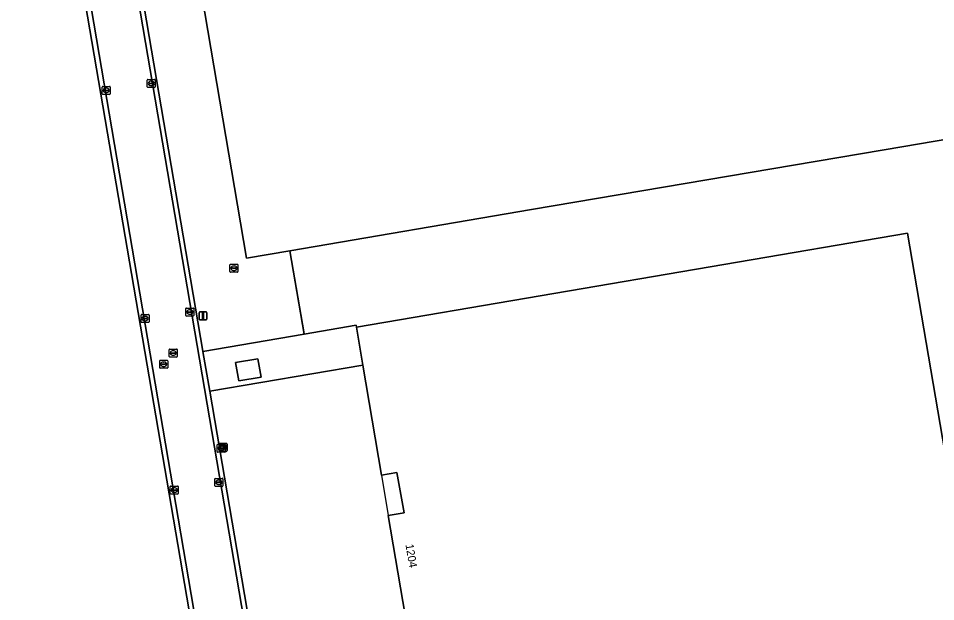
# Model space of a CAD drawing. Extents: x 154324 to 155744, y 382937 to 384188.
# Drawn here: x 154705 to 154819.6, y 383454.6 to 383527.5 of the extents above; entities that cross this region are included whole.
import ezdxf

# ---------------------------------------------------------------- set-up
doc = ezdxf.new("R2010")
doc.units = 0
for name, color, linetype in [('IMGEO_Brandkraan', 7, 'Continuous'), ('IMGEO_Erf', 7, 'Continuous'), ('IMGEO_Groenvoorziening', 7, 'Continuous'), ('IMGEO_Hek', 7, 'Continuous'), ('IMGEO_Kolk', 7, 'Continuous'), ('IMGEO_Lage_trafo', 7, 'Continuous'), ('IMGEO_Lichtmast', 7, 'Continuous'), ('IMGEO_Pand', 7, 'Continuous'), ('IMGEO_Pand_nummerreeks', 7, 'Continuous'), ('IMGEO_Pand_overbouw', 7, 'Continuous'), ('IMGEO_Parkeervlak_open', 7, 'Continuous'), ('IMGEO_Rijbaan_lokaal_gesloten', 7, 'Continuous'), ('IMGEO_Rijbaan_lokaal_open', 7, 'Continuous'), ('IMGEO_Rioolput', 7, 'Continuous'), ('IMGEO_Terreindeel_open', 7, 'Continuous'), ('IMGEO_Verklikker', 7, 'Continuous'), ('IMGEO_Voetpad_open', 7, 'Continuous')]:
    doc.layers.add(name, color=color, linetype=linetype)

msp = doc.modelspace()

# ---------------------------------------------------------------- linework, layer by layer
at = {"layer": 'IMGEO_Brandkraan'}
for p, q in [((154729.88, 383473.37), (154729.88, 383474.22)), ((154729.95, 383474.29), (154730.8, 383474.29)), ((154730.8, 383473.29), (154729.95, 383473.29)), ((154730.13, 383473.79), (154730.13, 383473.8)), ((154730.57, 383473.75), (154730.17, 383473.75)), ((154730.18, 383473.84), (154730.58, 383473.84)), ((154730.36, 383474.07), (154730.39, 383474.07)), ((154730.39, 383473.51), (154730.36, 383473.51)), ((154730.62, 383473.8), (154730.62, 383473.79)), ((154730.88, 383474.22), (154730.88, 383473.37))]:
    msp.add_line(p, q, dxfattribs=at)
for points in [[(154729.88, 383473.37), (154729.88, 383474.22)], [(154729.95, 383474.29), (154730.8, 383474.29)], [(154730.8, 383473.29), (154729.95, 383473.29)], [(154730.88, 383474.22), (154730.88, 383473.37)]]:
    msp.add_lwpolyline(points, dxfattribs=at)
for centre, radius, start, end in [((154729.95, 383474.22), 0.0765, 91.552, 178.448), ((154729.95, 383474.22), 0.0765, 91.552, 178.448), ((154729.95, 383473.37), 0.0765, 181.552, 268.448), ((154729.95, 383473.37), 0.0765, 181.552, 268.448), ((154730.18, 383473.8), 0.0403, 85.8775, 175.7526), ((154730.17, 383473.79), 0.0366, 178.938, 274.7102), ((154730.58, 383473.79), 0.043, 264.8664, 352.4533), ((154730.58, 383473.8), 0.0386, 1.7309, 96.639), ((154730.8, 383474.22), 0.0765, 1.552, 88.448), ((154730.8, 383474.22), 0.0765, 1.552, 88.448), ((154730.8, 383473.37), 0.0765, 271.552, 358.448), ((154730.8, 383473.37), 0.0765, 271.552, 358.448)]:
    msp.add_arc(centre, radius, start, end, dxfattribs=at)
for centre, major_axis, ratio, start_param, end_param in [((154730.36, 383473.79), (-0.387, 0.002), 0.722429, 4.712389, 7.853982), ((154730.39, 383473.79), (-0.39, 0.002), 0.717154, 1.570796, 4.712389)]:
    msp.add_ellipse(centre, major_axis=major_axis, ratio=ratio, start_param=start_param, end_param=end_param, dxfattribs=at)
at = {"layer": 'IMGEO_Erf'}
msp.add_lwpolyline([(154895.55, 383525.1), (154815.63, 383511.49), (154769.14, 383503.59), (154738.94, 383498.45), (154740.73, 383488.05), (154747.21, 383489.16), (154747.25, 383488.9), (154816.1, 383500.63), (154832.97, 383401.91), (154774.29, 383391.51), (154774.27, 383391.62), (154764.11, 383389.85), (154762.79, 383389.63), (154771.19, 383339.88), (154753.52, 383336.76), (154753.64, 383336.06), (154760.59, 383295.34), (154764.66, 383271.37), (154789.97, 383122.38), (154790.21, 383121.25)], dxfattribs=at)
at = {"layer": 'IMGEO_Groenvoorziening'}
msp.add_lwpolyline([(154736.07, 383396.59), (154735.43, 383400.34), (154733.72, 383410.4), (154733.05, 383414.37), (154731.57, 383423.07), (154705.98, 383572.84)], dxfattribs=at)
at = {"layer": 'IMGEO_Hek'}
msp.add_lwpolyline([(154738.94, 383498.45), (154740.73, 383488.07)], dxfattribs=at)
at = {"layer": 'IMGEO_Kolk'}
for p, q in [((154721.13, 383518.92), (154721.13, 383519.77)), ((154721.2, 383519.84), (154722.06, 383519.84)), ((154721.39, 383519.34), (154721.39, 383519.35)), ((154721.43, 383519.39), (154721.83, 383519.39)), ((154721.83, 383519.3), (154721.43, 383519.3)), ((154721.62, 383519.62), (154721.64, 383519.62)), ((154721.64, 383519.06), (154721.62, 383519.06)), ((154721.87, 383519.35), (154721.87, 383519.34)), ((154722.13, 383519.77), (154722.13, 383518.92)), ((154715.5, 383518.05), (154715.5, 383518.9)), ((154715.57, 383518.98), (154716.43, 383518.98)), ((154716.43, 383517.98), (154715.57, 383517.98)), ((154715.76, 383518.47), (154715.76, 383518.48)), ((154715.8, 383518.52), (154716.2, 383518.52)), ((154716.2, 383518.43), (154715.8, 383518.43)), ((154715.99, 383518.76), (154716.01, 383518.76)), ((154716.01, 383518.2), (154715.99, 383518.2)), ((154716.24, 383518.48), (154716.24, 383518.47)), ((154716.5, 383518.9), (154716.5, 383518.05)), ((154722.06, 383518.84), (154721.2, 383518.84)), ((154720.35, 383489.57), (154720.35, 383490.42)), ((154720.42, 383490.49), (154721.28, 383490.49)), ((154721.35, 383490.42), (154721.35, 383489.57)), ((154725.95, 383490.37), (154725.95, 383491.23)), ((154726.02, 383491.3), (154726.87, 383491.3)), ((154726.2, 383490.79), (154726.2, 383490.81)), ((154726.64, 383490.76), (154726.24, 383490.76)), ((154726.25, 383490.84), (154726.64, 383490.84)), ((154726.43, 383491.08), (154726.46, 383491.08)), ((154726.46, 383490.52), (154726.43, 383490.52)), ((154726.69, 383490.81), (154726.69, 383490.79)), ((154726.95, 383491.23), (154726.95, 383490.37)), ((154721.28, 383489.49), (154720.42, 383489.49)), ((154720.61, 383489.99), (154720.61, 383490)), ((154720.65, 383490.04), (154721.05, 383490.04)), ((154721.05, 383489.95), (154720.65, 383489.95)), ((154720.86, 383489.71), (154720.83, 383489.71)), ((154720.84, 383490.27), (154720.86, 383490.27)), ((154721.09, 383490), (154721.09, 383489.99)), ((154726.87, 383490.3), (154726.02, 383490.3)), ((154729.57, 383469.11), (154729.57, 383469.96)), ((154729.65, 383470.03), (154730.5, 383470.03)), ((154730.06, 383469.81), (154730.09, 383469.81)), ((154730.57, 383469.96), (154730.57, 383469.11)), ((154724, 383468.14), (154724, 383469)), ((154724.07, 383469.07), (154724.93, 383469.07)), ((154724.26, 383468.56), (154724.26, 383468.58)), ((154724.3, 383468.61), (154724.7, 383468.61)), ((154724.49, 383468.85), (154724.51, 383468.85)), ((154724.74, 383468.58), (154724.74, 383468.56)), ((154725, 383469), (154725, 383468.14)), ((154730.5, 383469.03), (154729.65, 383469.03)), ((154729.83, 383469.53), (154729.83, 383469.54)), ((154729.87, 383469.58), (154730.27, 383469.58)), ((154730.27, 383469.49), (154729.87, 383469.49)), ((154730.08, 383469.25), (154730.06, 383469.25)), ((154730.32, 383469.54), (154730.32, 383469.53)), ((154724.93, 383468.07), (154724.07, 383468.07)), ((154724.69, 383468.53), (154724.3, 383468.53)), ((154724.51, 383468.29), (154724.48, 383468.29))]:
    msp.add_line(p, q, dxfattribs=at)
for points in [[(154721.13, 383518.92), (154721.13, 383519.77)], [(154721.2, 383519.84), (154722.06, 383519.84)], [(154722.13, 383519.77), (154722.13, 383518.92)], [(154715.5, 383518.05), (154715.5, 383518.9)], [(154715.57, 383518.98), (154716.43, 383518.98)], [(154716.43, 383517.98), (154715.57, 383517.98)], [(154716.5, 383518.9), (154716.5, 383518.05)], [(154722.06, 383518.84), (154721.2, 383518.84)], [(154720.35, 383489.57), (154720.35, 383490.42)], [(154720.42, 383490.49), (154721.28, 383490.49)], [(154721.35, 383490.42), (154721.35, 383489.57)], [(154725.95, 383490.37), (154725.95, 383491.23)], [(154726.02, 383491.3), (154726.87, 383491.3)], [(154726.95, 383491.23), (154726.95, 383490.37)], [(154721.28, 383489.49), (154720.42, 383489.49)], [(154726.87, 383490.3), (154726.02, 383490.3)], [(154729.57, 383469.11), (154729.57, 383469.96)], [(154729.65, 383470.03), (154730.5, 383470.03)], [(154730.57, 383469.96), (154730.57, 383469.11)], [(154724, 383468.14), (154724, 383469)], [(154724.07, 383469.07), (154724.93, 383469.07)], [(154725, 383469), (154725, 383468.14)], [(154730.5, 383469.03), (154729.65, 383469.03)], [(154724.93, 383468.07), (154724.07, 383468.07)]]:
    msp.add_lwpolyline(points, dxfattribs=at)
for centre, radius, start, end in [((154721.21, 383519.77), 0.0765, 91.552, 178.448), ((154721.21, 383519.77), 0.0765, 91.552, 178.448), ((154721.43, 383519.35), 0.0403, 85.8775, 175.7526), ((154721.43, 383519.34), 0.0366, 178.938, 274.7102), ((154721.83, 383519.35), 0.0386, 1.7309, 96.639), ((154721.83, 383519.34), 0.043, 264.8664, 352.4533), ((154722.05, 383519.77), 0.0765, 1.552, 88.448), ((154722.05, 383519.77), 0.0765, 1.552, 88.448), ((154715.58, 383518.9), 0.0765, 91.552, 178.448), ((154715.58, 383518.9), 0.0765, 91.552, 178.448), ((154715.58, 383518.05), 0.0765, 181.552, 268.448), ((154715.58, 383518.05), 0.0765, 181.552, 268.448), ((154715.8, 383518.48), 0.0403, 85.8775, 175.7526), ((154715.8, 383518.47), 0.0366, 178.938, 274.7102), ((154716.2, 383518.48), 0.0386, 1.7309, 96.639), ((154716.2, 383518.48), 0.043, 264.8664, 352.4533), ((154716.42, 383518.9), 0.0765, 1.552, 88.448), ((154716.42, 383518.9), 0.0765, 1.552, 88.448), ((154716.42, 383518.05), 0.0765, 271.552, 358.448), ((154716.42, 383518.05), 0.0765, 271.552, 358.448), ((154721.21, 383518.92), 0.0765, 181.552, 268.448), ((154721.21, 383518.92), 0.0765, 181.552, 268.448), ((154722.05, 383518.92), 0.0765, 271.552, 358.448), ((154722.05, 383518.92), 0.0765, 271.552, 358.448), ((154720.43, 383490.42), 0.0765, 91.552, 178.448), ((154720.43, 383490.42), 0.0765, 91.552, 178.448), ((154721.27, 383490.42), 0.0765, 1.552, 88.448), ((154721.27, 383490.42), 0.0765, 1.552, 88.448), ((154726.02, 383491.22), 0.0765, 91.552, 178.448), ((154726.02, 383491.22), 0.0765, 91.552, 178.448), ((154726.02, 383490.37), 0.0765, 181.552, 268.448), ((154726.02, 383490.37), 0.0765, 181.552, 268.448), ((154726.24, 383490.8), 0.0403, 85.8775, 175.7526), ((154726.24, 383490.79), 0.0366, 178.938, 274.7102), ((154726.65, 383490.8), 0.0386, 1.7309, 96.639), ((154726.65, 383490.8), 0.043, 264.8664, 352.4533), ((154726.87, 383491.22), 0.0765, 1.552, 88.448), ((154726.87, 383491.22), 0.0765, 1.552, 88.448), ((154726.87, 383490.37), 0.0765, 271.552, 358.448), ((154726.87, 383490.37), 0.0765, 271.552, 358.448), ((154720.43, 383489.57), 0.0765, 181.552, 268.448), ((154720.43, 383489.57), 0.0765, 181.552, 268.448), ((154720.65, 383490), 0.0403, 85.8775, 175.7526), ((154720.64, 383489.99), 0.0366, 178.938, 274.7102), ((154721.05, 383490), 0.0386, 1.7309, 96.639), ((154721.05, 383489.99), 0.043, 264.8664, 352.4533), ((154721.27, 383489.57), 0.0765, 271.552, 358.448), ((154721.27, 383489.57), 0.0765, 271.552, 358.448), ((154729.65, 383469.96), 0.0765, 91.552, 178.448), ((154729.65, 383469.96), 0.0765, 91.552, 178.448), ((154730.5, 383469.96), 0.0765, 1.552, 88.448), ((154730.5, 383469.96), 0.0765, 1.552, 88.448), ((154724.07, 383469), 0.0765, 91.552, 178.448), ((154724.07, 383469), 0.0765, 91.552, 178.448), ((154724.3, 383468.57), 0.0403, 85.8775, 175.7526), ((154724.7, 383468.58), 0.0386, 1.7309, 96.639), ((154724.92, 383469), 0.0765, 1.552, 88.448), ((154724.92, 383469), 0.0765, 1.552, 88.448), ((154729.65, 383469.11), 0.0765, 181.552, 268.448), ((154729.65, 383469.11), 0.0765, 181.552, 268.448), ((154729.87, 383469.54), 0.0403, 85.8775, 175.7526), ((154729.87, 383469.53), 0.0366, 178.938, 274.7102), ((154730.28, 383469.54), 0.0386, 1.7309, 96.639), ((154730.27, 383469.53), 0.043, 264.8664, 352.4533), ((154730.5, 383469.11), 0.0765, 271.552, 358.448), ((154730.5, 383469.11), 0.0765, 271.552, 358.448), ((154724.07, 383468.15), 0.0765, 181.552, 268.448), ((154724.07, 383468.15), 0.0765, 181.552, 268.448), ((154724.29, 383468.56), 0.0366, 178.938, 274.7102), ((154724.7, 383468.57), 0.043, 264.8664, 352.4533), ((154724.92, 383468.15), 0.0765, 271.552, 358.448), ((154724.92, 383468.15), 0.0765, 271.552, 358.448)]:
    msp.add_arc(centre, radius, start, end, dxfattribs=at)
for centre, major_axis, ratio, start_param, end_param in [((154721.62, 383519.34), (-0.387, 0.002), 0.722429, 4.712389, 7.853982), ((154721.64, 383519.34), (-0.39, 0.002), 0.717154, 1.570796, 4.712389), ((154715.99, 383518.48), (-0.387, 0.002), 0.722429, 4.712389, 7.853982), ((154716.01, 383518.48), (-0.39, 0.002), 0.717154, 1.570796, 4.712389), ((154726.43, 383490.8), (-0.387, 0.002), 0.722429, 4.712389, 7.853982), ((154726.46, 383490.8), (-0.39, 0.002), 0.717154, 1.570796, 4.712389), ((154720.84, 383489.99), (-0.387, 0.002), 0.722429, 4.712389, 7.853982), ((154720.86, 383489.99), (-0.39, 0.002), 0.717154, 1.570796, 4.712389), ((154730.06, 383469.53), (-0.387, 0.002), 0.722429, 4.712389, 7.853982), ((154730.08, 383469.53), (-0.39, 0.002), 0.717154, 1.570796, 4.712389), ((154724.49, 383468.57), (-0.387, 0.002), 0.722429, 4.712389, 7.853982), ((154724.51, 383468.57), (-0.39, 0.002), 0.717154, 1.570796, 4.712389)]:
    msp.add_ellipse(centre, major_axis=major_axis, ratio=ratio, start_param=start_param, end_param=end_param, dxfattribs=at)
at = {"layer": 'IMGEO_Lage_trafo'}
msp.add_lwpolyline([(154734.96, 383484.97), (154732.15, 383484.49), (154732.55, 383482.19), (154735.36, 383482.68)], close=True, dxfattribs=at)
at = {"layer": 'IMGEO_Lichtmast'}
for p, q in [((154727.6, 383489.92), (154727.6, 383490.72)), ((154727.6, 383490.72), (154727.6, 383489.92)), ((154727.7, 383490.82), (154728.49, 383490.82)), ((154728.49, 383490.82), (154727.7, 383490.82)), ((154728.59, 383490.72), (154728.59, 383489.92)), ((154728.59, 383489.92), (154728.59, 383490.72)), ((154728.49, 383489.82), (154727.7, 383489.82)), ((154727.7, 383489.82), (154728.49, 383489.82))]:
    msp.add_line(p, q, dxfattribs=at)
msp.add_lwpolyline([(154728.02, 383490.7), (154728.17, 383490.7), (154728.17, 383489.95), (154728.02, 383489.95), (154728.02, 383490.7)], dxfattribs=at)
for centre, start, end in [((154727.7, 383490.72), 90, 180), ((154727.7, 383490.72), 90, 180), ((154728.49, 383490.72), 0, 90), ((154728.49, 383490.72), 360, 90), ((154727.7, 383489.92), 180, 270), ((154727.7, 383489.92), 180, 270), ((154728.49, 383489.92), 270, 0), ((154728.49, 383489.92), 270, 0)]:
    msp.add_arc(centre, 0.1, start, end, dxfattribs=at)
at = {"layer": 'IMGEO_Pand'}
for points in [[(154879.18, 383621.22), (154809.97, 383609.47), (154807.03, 383626.73), (154796.3, 383624.97), (154799.26, 383607.57), (154717.25, 383593.65), (154717.21, 383593.64), (154733.53, 383497.52), (154738.94, 383498.45), (154769.14, 383503.59), (154815.63, 383511.49), (154895.55, 383525.1)], [(154816.1, 383500.63), (154747.25, 383488.9), (154748.06, 383484.15), (154750.39, 383470.42), (154752.32, 383470.75), (154753.23, 383465.74), (154751.24, 383465.4), (154754.6, 383445.61), (154754.64, 383445.37), (154764.83, 383447.08), (154774.24, 383391.82), (154774.27, 383391.62), (154774.29, 383391.51), (154832.97, 383401.91)]]:
    msp.add_lwpolyline(points, close=True, dxfattribs=at)
at = {"layer": 'IMGEO_Pand_overbouw'}
msp.add_lwpolyline([(154750.39, 383470.42), (154751.24, 383465.4), (154753.23, 383465.74), (154752.32, 383470.75)], close=True, dxfattribs=at)
at = {"layer": 'IMGEO_Parkeervlak_open'}
msp.add_lwpolyline([(154751.24, 383465.4), (154753.23, 383465.74), (154752.32, 383470.75), (154750.39, 383470.42), (154748.06, 383484.15), (154728.93, 383480.92), (154752.34, 383343.73), (154753.52, 383336.76), (154771.19, 383339.88), (154762.79, 383389.63), (154748.9, 383387.22), (154747.39, 383385.1), (154747.35, 383385.12), (154747.11, 383385.08), (154737.3, 383442.45), (154737.26, 383442.66), (154754.6, 383445.61)], close=True, dxfattribs=at)
at = {"layer": 'IMGEO_Rijbaan_lokaal_gesloten'}
for points in [[(154678.7, 383732.94), (154679.41, 383729.15), (154695.21, 383636.16), (154695.76, 383632.98), (154705.98, 383572.84), (154731.57, 383423.07), (154733.05, 383414.37), (154733.72, 383410.4), (154735.43, 383400.34), (154736.07, 383396.59), (154752.1, 383302.29), (154752.65, 383299.07), (154768.89, 383203.55), (154782.92, 383120.99), (154783.08, 383120.12), (154784.08, 383114.24), (154785.08, 383108.27)], [(154679.26, 383733.15), (154679.93, 383729.19), (154748.65, 383326.31), (154783.5, 383121.23), (154783.65, 383120.27), (154785.66, 383108.36)], [(154785.66, 383108.36), (154783.65, 383120.27), (154783.5, 383121.23), (154748.65, 383326.31), (154679.93, 383729.19), (154679.26, 383733.15)], [(154789.63, 383121.11), (154789.03, 383124.4), (154786.39, 383140.02), (154764.04, 383271.32), (154739.67, 383414.35), (154710.41, 383586)]]:
    msp.add_lwpolyline(points, dxfattribs=at)
at = {"layer": 'IMGEO_Rijbaan_lokaal_open'}
for points in [[(154790.21, 383121.25), (154789.97, 383122.38), (154764.66, 383271.37), (154760.59, 383295.34), (154753.64, 383336.06), (154753.52, 383336.76), (154752.34, 383343.73), (154728.93, 383480.92), (154728.09, 383485.86), (154728.08, 383485.9), (154713.13, 383573.57), (154707.83, 383604.93), (154701.97, 383639.51), (154695.82, 383675.91), (154684.79, 383740.24)], [(154684.2, 383740.13), (154685.55, 383732.21), (154710.41, 383586), (154739.67, 383414.35), (154764.04, 383271.32), (154786.39, 383140.02), (154789.03, 383124.4), (154789.63, 383121.11)]]:
    msp.add_lwpolyline(points, dxfattribs=at)
at = {"layer": 'IMGEO_Rioolput'}
for p, q in [((154731.46, 383495.85), (154731.46, 383496.7)), ((154731.53, 383496.77), (154732.39, 383496.77)), ((154731.72, 383496.27), (154731.72, 383496.28)), ((154731.76, 383496.32), (154732.16, 383496.32)), ((154732.16, 383496.23), (154731.76, 383496.23)), ((154731.95, 383496.55), (154731.97, 383496.55)), ((154732.2, 383496.28), (154732.2, 383496.27)), ((154732.46, 383496.7), (154732.46, 383495.85)), ((154732.39, 383495.77), (154731.53, 383495.77)), ((154731.97, 383495.99), (154731.94, 383495.99)), ((154723.87, 383485.25), (154723.87, 383486.11)), ((154723.94, 383486.18), (154724.8, 383486.18)), ((154724.36, 383485.96), (154724.38, 383485.96)), ((154724.87, 383486.11), (154724.87, 383485.25)), ((154722.68, 383483.85), (154722.68, 383484.7)), ((154722.75, 383484.78), (154723.61, 383484.78)), ((154723.68, 383484.7), (154723.68, 383483.85)), ((154724.8, 383485.18), (154723.94, 383485.18)), ((154724.13, 383485.67), (154724.13, 383485.69)), ((154724.17, 383485.72), (154724.57, 383485.72)), ((154724.57, 383485.64), (154724.17, 383485.64)), ((154724.38, 383485.4), (154724.35, 383485.4)), ((154724.61, 383485.69), (154724.61, 383485.67)), ((154723.61, 383483.78), (154722.75, 383483.78)), ((154722.94, 383484.27), (154722.94, 383484.28)), ((154722.98, 383484.32), (154723.38, 383484.32)), ((154723.38, 383484.23), (154722.98, 383484.23)), ((154723.17, 383484.56), (154723.19, 383484.56)), ((154723.19, 383484), (154723.17, 383484)), ((154723.42, 383484.28), (154723.42, 383484.27))]:
    msp.add_line(p, q, dxfattribs=at)
for points in [[(154731.46, 383495.85), (154731.46, 383496.7)], [(154731.53, 383496.77), (154732.39, 383496.77)], [(154732.46, 383496.7), (154732.46, 383495.85)], [(154732.39, 383495.77), (154731.53, 383495.77)], [(154723.87, 383485.25), (154723.87, 383486.11)], [(154723.94, 383486.18), (154724.8, 383486.18)], [(154724.87, 383486.11), (154724.87, 383485.25)], [(154722.68, 383483.85), (154722.68, 383484.7)], [(154722.75, 383484.78), (154723.61, 383484.78)], [(154723.68, 383484.7), (154723.68, 383483.85)], [(154724.8, 383485.18), (154723.94, 383485.18)], [(154723.61, 383483.78), (154722.75, 383483.78)]]:
    msp.add_lwpolyline(points, dxfattribs=at)
for centre, radius, start, end in [((154731.54, 383496.7), 0.0765, 91.552, 178.448), ((154731.54, 383496.7), 0.0765, 91.552, 178.448), ((154731.76, 383496.28), 0.0403, 85.8775, 175.7526), ((154731.75, 383496.27), 0.0366, 178.938, 274.7102), ((154732.16, 383496.28), 0.0386, 1.7309, 96.639), ((154732.16, 383496.27), 0.043, 264.8664, 352.4533), ((154732.38, 383496.7), 0.0765, 1.552, 88.448), ((154732.38, 383496.7), 0.0765, 1.552, 88.448), ((154731.54, 383495.85), 0.0765, 181.552, 268.448), ((154731.54, 383495.85), 0.0765, 181.552, 268.448), ((154732.38, 383495.85), 0.0765, 271.552, 358.448), ((154732.38, 383495.85), 0.0765, 271.552, 358.448), ((154723.95, 383486.1), 0.0765, 91.552, 178.448), ((154723.95, 383486.1), 0.0765, 91.552, 178.448), ((154724.79, 383486.1), 0.0765, 1.552, 88.448), ((154724.79, 383486.1), 0.0765, 1.552, 88.448), ((154722.76, 383484.7), 0.0765, 91.552, 178.448), ((154722.76, 383484.7), 0.0765, 91.552, 178.448), ((154723.6, 383484.7), 0.0765, 1.552, 88.448), ((154723.6, 383484.7), 0.0765, 1.552, 88.448), ((154723.95, 383485.26), 0.0765, 181.552, 268.448), ((154723.95, 383485.26), 0.0765, 181.552, 268.448), ((154724.17, 383485.68), 0.0403, 85.8775, 175.7526), ((154724.16, 383485.67), 0.0366, 178.938, 274.7102), ((154724.57, 383485.68), 0.0386, 1.7309, 96.639), ((154724.57, 383485.68), 0.043, 264.8664, 352.4533), ((154724.79, 383485.26), 0.0765, 271.552, 358.448), ((154724.79, 383485.26), 0.0765, 271.552, 358.448), ((154722.76, 383483.85), 0.0765, 181.552, 268.448), ((154722.76, 383483.85), 0.0765, 181.552, 268.448), ((154722.98, 383484.28), 0.0403, 85.8775, 175.7526), ((154722.98, 383484.27), 0.0366, 178.938, 274.7102), ((154723.38, 383484.28), 0.0386, 1.7309, 96.639), ((154723.38, 383484.28), 0.043, 264.8664, 352.4533), ((154723.6, 383483.85), 0.0765, 271.552, 358.448), ((154723.6, 383483.85), 0.0765, 271.552, 358.448)]:
    msp.add_arc(centre, radius, start, end, dxfattribs=at)
for centre, major_axis, ratio, start_param, end_param in [((154731.95, 383496.27), (-0.387, 0.002), 0.722429, 4.712389, 7.853982), ((154731.97, 383496.27), (-0.39, 0.002), 0.717154, 1.570796, 4.712389), ((154724.36, 383485.68), (-0.387, 0.002), 0.722429, 4.712389, 7.853982), ((154724.38, 383485.68), (-0.39, 0.002), 0.717154, 1.570796, 4.712389), ((154723.17, 383484.28), (-0.387, 0.002), 0.722429, 4.712389, 7.853982), ((154723.19, 383484.28), (-0.39, 0.002), 0.717154, 1.570796, 4.712389)]:
    msp.add_ellipse(centre, major_axis=major_axis, ratio=ratio, start_param=start_param, end_param=end_param, dxfattribs=at)
at = {"layer": 'IMGEO_Terreindeel_open'}
msp.add_lwpolyline([(154717.21, 383593.64), (154717.25, 383593.65), (154715.12, 383606.17), (154707.83, 383604.93), (154713.13, 383573.57), (154728.08, 383485.9), (154728.09, 383485.86), (154740.73, 383488.05), (154738.94, 383498.45), (154733.53, 383497.52)], close=True, dxfattribs=at)
at = {"layer": 'IMGEO_Verklikker'}
for p, q in [((154730.21, 383474.4), (154731, 383474.4)), ((154731, 383474.4), (154730.21, 383474.4)), ((154730.11, 383473.5), (154730.11, 383474.3)), ((154730.11, 383474.3), (154730.11, 383473.5)), ((154731, 383473.4), (154730.21, 383473.4)), ((154730.21, 383473.4), (154731, 383473.4)), ((154731.1, 383474.3), (154731.1, 383473.5)), ((154731.1, 383473.5), (154731.1, 383474.3))]:
    msp.add_line(p, q, dxfattribs=at)
for points in [[(154730.21, 383474.13), (154731, 383474.13), (154731, 383473.67), (154730.21, 383473.67), (154730.21, 383474.13)], [(154730.27, 383474.07), (154730.27, 383473.73), (154730.93, 383473.73), (154730.93, 383474.07), (154730.27, 383474.07)]]:
    msp.add_lwpolyline(points, dxfattribs=at)
for centre, start, end in [((154730.21, 383474.3), 90, 180), ((154730.21, 383474.3), 90, 180), ((154731, 383474.3), 0, 90), ((154731, 383474.3), 360, 90), ((154730.21, 383473.5), 180, 270), ((154730.21, 383473.5), 180, 270), ((154731, 383473.5), 270, 0), ((154731, 383473.5), 270, 0)]:
    msp.add_arc(centre, 0.1, start, end, dxfattribs=at)
at = {"layer": 'IMGEO_Voetpad_open'}
for points in [[(154747.25, 383488.9), (154747.21, 383489.16), (154740.73, 383488.05), (154728.09, 383485.86), (154728.93, 383480.92), (154748.06, 383484.15)], [(154735.36, 383482.68), (154732.55, 383482.19), (154732.15, 383484.49), (154734.96, 383484.97)]]:
    msp.add_lwpolyline(points, close=True, dxfattribs=at)

# ---------------------------------------------------------------- texts
at = {"layer": 'IMGEO_Pand_nummerreeks'}
msp.add_text('1204', height=1, rotation=279.6369, dxfattribs=at).set_placement((154753.38, 383461.75))

doc.saveas('drawing.dxf')
